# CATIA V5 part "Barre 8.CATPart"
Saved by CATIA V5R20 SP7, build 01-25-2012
Part number: Barre 8
Bounding box of the stored display mesh (mm): x -9.981 to 244.921, y -179.988 to 211.787, z 10 to 20
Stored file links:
  D:\thinkmotion-MPB\Dropbox\IAO_2012\IAO_2012_714_mperrusset\IAO_2012_714_mperrusset\mperrusset\Barre 8.CATPart
  C:\Users\Matthieu\Desktop\IFMA\Cours 2A\Thinkmotion\Ass_skl_IAO.CATProduct
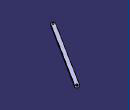
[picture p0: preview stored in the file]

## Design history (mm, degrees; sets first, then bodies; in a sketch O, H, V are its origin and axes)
AxisSystem1: origin (0, 0, 0), X (1, 0, 0), Y (0, 1, 0), Z (0, 0, 1)
Set1
  Plane1 "Plan_Ref": linked copy from another document
  Line1 "Barre_8": linked copy from another document
  Line2 "Axe_Pivot_b8b4": linked copy from another document
  Line3 "Axe_Pivot_b8b7": linked copy from another document
  Point1 "Point.N": linked copy from another document
Body1 (main body)
  Sketch1 on Plane1, origin (0, 0, 0), H (1, 0, 0), V (0, 1, 0)
    line L1 (243.3769, 196.4502) -> (8.4538, -175.3417)
    arc A1 centre (0, -170) radius 10 from (8.4538, -175.3417) to (-8.3064, -164.4319) cw
    point P3 (0, -170)
    line L2 (-8.3064, -164.4319) -> (226.6168, 207.36)
    arc A2 centre (234.9232, 201.7919) radius 10 from (226.6168, 207.36) to (243.3769, 196.4502) cw
    point P6 (234.9232, 201.7919)
    reference projected line E1 (0, -170) -> (234.9232, 201.7919) from Line1
    reference projected line E2 (0, -170) -> (234.9232, 201.7919) from Line1
    reference projected point E3 (234.9232, 201.7919) from Line2
    reference projected point E4 (0, -170) from Line3
    circle A3 centre (0, -170) radius 5
    circle A4 centre (234.9232, 201.7919) radius 5
    distance P6 A2 = 10
    distance P3 A1 = 10
    radius A3 = 5
    radius A4 = 5
    tangency: A1 L1
    parallelism: E1 L1, E2 L2
    coincidence: P6 E3, P3 E4
  Pad1: profile Sketch1, direction (0, 0, 1), length 20, opposite side length -10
